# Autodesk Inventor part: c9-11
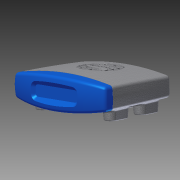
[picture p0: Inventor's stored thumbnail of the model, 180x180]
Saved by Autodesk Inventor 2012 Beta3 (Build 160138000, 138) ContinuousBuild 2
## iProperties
Created: 2010-12
Part Number: c9-11
Material: Default
Document SubType Name: Modeling
Designer: Beta-8540w
Density: 1 g/cm^3
Author: Beta-8540w
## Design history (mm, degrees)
sketch "Sketch1"
  geometry: L1 (-60, -12)-(60, -12); L2 (60, -12)-(60, 12); L3 (60, 12)-(-60, 12); L4 (-60, 12)-(-60, -12); A1 r 350 centre (0, -332.819) between (60, 12) and (-60, 12); A2 r 350 centre (0, 332.819) between (-60, -12) and (60, -12); 3 further points
  constraints: 8 end point, 4 point on circle, 2 centre point, 2 midpoint, 2 parallel, 1 equal radius, 1 horizontal, 1 horizontal alignment, 1 perpendicular, 1 vertical alignment
  dimensions: "d0" = 120 distance of L3.end L2.end; "d1" = 24 distance of L2.end L1.end; "d2" = 350 radius of A1
workplane "Work Plane4"
sketch "Sketch5"
  geometry: L1 (-60, 12)-(-60, -12) reference; L2 (60, -12)-(60, 12) reference; L3 (-58, 10.314)-(-58, -10.314); L4 (58, -10.314)-(58, 10.314); A1 r 350 centre (0, 332.819) between (-60, -12) and (60, -12) reference; A2 r 350 centre (0, -332.819) between (60, 12) and (-60, 12) reference; A3 r 348 centre (0, 332.819) between (-58, -10.314) and (58, -10.314); A4 r 348 centre (0, -332.819) between (58, 10.314) and (-58, 10.314); 1 further point
  constraints: 4 end point, 4 point on circle, 2 centre point, 3 other
  dimensions: "d37" = 2 distance between parallel lines of L2 L4
sketch "Sketch6"
  geometry: L1 (-60, 0)-(60, 0); L2 (60, 0)-(58.843, 22.085); L3 (-60, 0)-(-58.779, 23.307); A1 r 691.758 centre (630.81, -36.204) between (-60, 0) and (-58, -100); A2 r 691.758 centre (-630.81, -36.204) between (58, -100) and (60, 0); 1 further point
  constraints: 6 end point, 4 point on circle, 2 centre point, 2 tangent, 1 horizontal
  dimensions: "d53" = 87 deg angle of L1 L3; "d54" = 87 deg angle of L1 L2 (= d53)
sketch "Sketch7"
  geometry: L1 (17.181, 0)-(12, 0) reference; L2 (15.181, -100)-(10.314, -100) reference; L3 (17.181, 0)-(16.768, 11.838); A1 r 911.322 centre (-893.585, -31.805) between (15.181, -100) and (17.181, 0); 1 further point
  constraints: 2 end point, 2 point on circle, 1 centre point, 1 tangent
  dimensions: "d56" = 88 deg angle of L1 L3
feature "LoftSrf2" sketch "Sketch5", "Sketch6", "Sketch7" dims "d57" = 0, "d58" = 90 deg, "d59" = 0, "d60" = 90 deg, "d61" = 0, "d62" = 90 deg, "d63" = 0, "d64" = 90 deg, "d65" = 0, "d66" = 90 deg
sketch "Sketch2"
  geometry: L1 (-75, -16)-(75, -16); L2 (-75, -60)-(75, -60); A1 r 183.781 centre (0, -183.781) between (75, -16) and (-75, -16); 2 further points
  constraints: 4 end point, 3 point on circle, 1 centre point, 1 coincident, 1 horizontal, 1 parallel
  dimensions: "d5" = 16 distance from line of point (0, 0) L1; "d7" = 60 distance from line of point (0, 0) L2; "d55" = 150 distance of L1.start L1.end
feature "RevolutionSrf1" sketch "Sketch2" dims angle "d8" = 40 deg
patch "Boundary Patch1" dims "d13" = 0, "d67" = 0, "d68" = 0, "d69" = 0, "d70" = 0
workplane "Work Plane1"
sketch "Sketch3"
  geometry: L1 (52, -85)-(52, -73); L2 (38, -73)-(38, -85); A1 r 7 centre (45, -73) between (52, -73) and (38, -73); A2 r 7 centre (45, -85) between (38, -85) and (52, -85); 1 further point
  constraints: 4 end point, 4 point on circle, 4 tangent, 2 centre point, 1 parallel, 1 vertical
  dimensions: "d15" = 12 distance of L1.start L1.end; "d16" = 7 radius of A1; "d50" = 45 horizontal distance of A1.centre point (0, 0); "d51" = 85 vertical distance of point (0, 0) A2.centre
extrude_surface "ExtrusionSrf2" sketch "Sketch3" dims "d19" = 14, "d20" = 5 deg
pattern_linear "Rectangular Pattern1" dims "d23" = 90
workplane "Work Plane2"
feature "Sculpt1"
sketch "Sketch4"
  geometry: L1 (-24.5, 6)-(24.5, 6); L2 (27.5, 3)-(27.5, -3); L3 (24.5, -6)-(-24.5, -6); L4 (-27.5, -3)-(-27.5, 3); A1 r 3 centre (-24.5, 3) between (-24.5, 6) and (-27.5, 3); A2 r 3 centre (24.5, 3) between (27.5, 3) and (24.5, 6); A3 r 3 centre (24.5, -3) between (24.5, -6) and (27.5, -3); A4 r 3 centre (-24.5, -3) between (-27.5, -3) and (-24.5, -6); 6 further points
  constraints: 8 end point, 8 point on circle, 8 tangent, 6 point on line, 4 centre point, 3 equal radius, 2 midpoint, 2 parallel, 1 horizontal, 1 horizontal alignment, 1 perpendicular, 1 vertical alignment
  dimensions: "d28" = 55 distance of point (27.5, -6) point (-27.5, -6); "d29" = 12 distance of point (27.5, 6) point (27.5, -6); "d30" = 3 radius of A1
extrude_surface "ExtrusionSrf6" sketch "Sketch4" dims "d31" = 14, "d32" = 45 deg
patch "Boundary Patch2" dims "d33" = 0, "d34" = 0
fillet "Fillet1" dims "d79" = 4, "d80" = 3, "d81" = 1
feature "Sculpt2"
node "Splitting Plane 1"
shell "Shell1" dims "d83" = 2
split "Split1"
  body "Solid1"
feature "Lip1" dims "d188" = 1, "d189" = 1, "d190" = 0, "d191" = 0, "d192" = 0, "d193" = 0
feature "Lip2" dims "d194" = 1, "d195" = 1, "d196" = 0, "d197" = 0, "d198" = 0, "d199" = 0.5
split "Split3"
  node "Back"
sketch "Sketch9"
  geometry: L1 (50.167, -73)-(50.167, -85) reference; L2 (39.833, -85)-(39.833, -73) reference; L3 (45, -73)-(45, -85); L4 (45, -85)-(39.833, -85); A1 r 5.167 centre (45, -73) between (50.167, -73) and (39.833, -73) reference; A2 r 5.167 centre (45, -85) between (39.833, -85) and (50.167, -85) reference; 5 further points
  constraints: 4 end point, 1 horizontal, 1 midpoint, 1 parallel, 1 perpendicular, 1 vertical, 3 other
  dimensions: "d86" = 90 distance of point (45, -79) point (-45, -79); "d89" = 40 distance of point (45, -79) point (45, -39)
  node "Projected Loop1"
feature "Boss1" dims "d92" = 0, "d93" = 0, "d94" = 7, "d95" = 2, "d96" = 0.5, "d97" = 6, "d98" = 1.25, "d99" = 3.5, "d100" = 2.5 deg, "d101" = 2.5 deg, "d102" = 2.5 deg, "d103" = 2.5 deg, "d104" = 90 deg, "d107" = 2, "d108" = 2, "d109" = 10, "d110" = 0, "d111" = 10 deg, "d112" = 2.5 deg, "d113" = 0, "d114" = 0, "d115" = 0, "d116" = 360 deg
feature "Boss2" dims "d117" = 3, "d118" = 0, "d119" = 6, "d120" = 3, "d121" = 9.5, "d122" = 2 deg, "d123" = 1 deg, "d126" = 2, "d127" = 2, "d128" = 10, "d129" = 0, "d130" = 10 deg, "d131" = 2.5 deg, "d132" = 0, "d133" = 0, "d134" = 0, "d135" = 360 deg
workplane "Work Plane6"
sketch "Sketch10"
  geometry: L1 (24, -85)-(-24, -85); L2 (-30, -79)-(-30, -51); L3 (-24, -45)-(24, -45); L4 (30, -51)-(30, -79); L5 (54.344, -100)-(-54.344, -100) reference; A1 r 6 centre (-24, -51) between (-24, -45) and (-30, -51); A2 r 6 centre (24, -51) between (30, -51) and (24, -45); A3 r 6 centre (24, -79) between (24, -85) and (30, -79); A4 r 6 centre (-24, -79) between (-30, -79) and (-24, -85); 5 further points
  constraints: 8 end point, 8 point on circle, 8 tangent, 6 point on line, 4 centre point, 3 equal radius, 2 parallel, 1 horizontal, 1 midpoint, 1 perpendicular, 1 vertical alignment
  dimensions: "d137" = 60 distance of point (-30, -45) point (30, -45); "d138" = 40 distance of point (-30, -85) point (-30, -45); "d139" = 15 distance between parallel lines of L5 L1; "d141" = 6 radius of A2
feature "Rest1" sketch "Sketch10" dims "d142" = 5, "d143" = 0, "d144" = 0, "d145" = 0, "d146" = 2 deg, "d147" = 2 deg, "d148" = 2
feature "Rule Fillet1" dims "d149" = 2, "d150" = 1
workplane "Work Plane7"
sketch "Sketch11" dims "d154" = 16, "d155" = 8, "d161" = 10, "d168" = 10
  geometry: L1 (-13, -39.858)-(-13, -90.142); L2 (-25.187, -85)-(29.449, -85); L3 (0, -39.858)-(0, -90.142); L4 (13, -39.858)-(13, -90.142); L5 (-25.187, -77)-(29.449, -77); L6 (-25.187, -69)-(29.449, -69); L7 (-25.187, -61)-(29.449, -61); L8 (-25.187, -53)-(29.449, -53); L9 (-25.187, -45)-(29.449, -45); C1 r 22.5 at (0, -65); 3 further points; 1 other entity
  constraints: 18 end point, 2 coincident, 2 vertical, 1 centre point, 1 horizontal, 1 midpoint, 1 perpendicular, 1 vertical alignment, 23 other
  dimensions: "d152" = 45 diameter of C1; "d153" = 65 distance of point (0, 0) C1.centre; "d158" = 13 distance of L1.start L3.start; "d165" = 8 distance of L2.start L5.start; "d170" = 4 distance from line of L7 point (0, -65)
feature "Grill1" sketch "Sketch11" dims "d173" = 2, "d174" = 0, "d175" = 1, "d176" = 2, "d177" = 0, "d178" = 1, "d179" = 0.5, "d180" = 0, "d181" = 2, "d182" = 1, "d183" = 2 deg, "d184" = 0, "d185" = 88.84492
sketch "Sketch12"
  geometry: L1 (-12.481, -61.203)-(12.401, -61.203); L2 (12.401, -61.203)-(12.401, -68.714); L3 (12.401, -68.714)-(-12.481, -68.714); L4 (-12.481, -68.714)-(-12.481, -61.203); 1 further point
  constraints: 2 other
emboss "Emboss1" sketch "Sketch12" dims "d186" = 0.5, "d187" = 0
sketch "Sketch13"
  geometry: L1 (0, 15.66)-(0, -14.781); 6 further points
  constraints: 2 end point, 1 coincident, 1 point on line, 1 vertical, 4 other
feature "Snap Fit1" sketch "Sketch13" dims "d200" = 4, "d201" = 2.5, "d202" = 1, "d203" = 0.9, "d204" = 10.2, "d205" = 10, "d206" = 1, "d207" = 1, "d208" = 50 deg, "d209" = 50 deg
fillet "Fillet2" dims "d213" = 2
workplane "Work Plane8"
sketch "Sketch14"
  geometry: L1 (-8.644, -6.828)-(57.644, -6.828); L2 (6.5, 3.689)-(6.5, -17.346); L3 (24.5, 3.689)-(24.5, -17.346); L4 (42.5, 3.689)-(42.5, -17.346); 2 further points
  constraints: 8 end point, 4 parallel, 2 horizontal alignment, 2 midpoint, 1 coincident, 1 horizontal, 1 perpendicular
  dimensions: "d211" = 18 distance between parallel lines of L3 L2; "d212" = 18 distance between parallel lines of L4 L3 (= d211)
feature "Rib1" sketch "Sketch14" dims "d214" = 2, "d215" = 1, "d216" = 5 deg, "d217" = 0, "d218" = 1, "d219" = 1
body "Srf2"
body "Srf3"
body "Srf4"
body "Srf5"
body "Srf6"
body "Srf7"
body "Srf8"
body "Srf9"
body "Srf11"
feature "Stitch Surface1"
body "Srf12"
extrude_surface "ExtrusionSrf3"
extrude_surface "ExtrusionSrf4"
extrude_surface "ExtrusionSrf5"
node "Front"
node "Back - Top"
node "Back - Bottom"
other parameters: "d14" = -24, "d52" = -6, "d171" = 1, "d172" = 2, "d210" = -1
